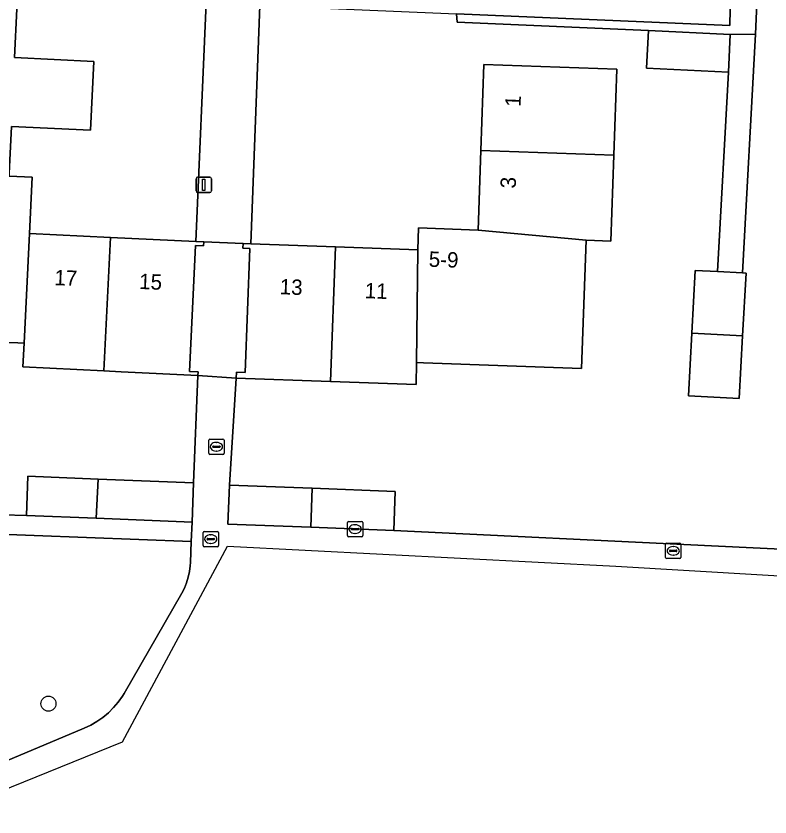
# Model space of a CAD drawing. Extents: x 158472 to 159562, y 388525 to 389606.
# Drawn here: x 159024.3 to 159073.4, y 388530.2 to 388582.4 of the extents above; entities that cross this region are included whole.
import ezdxf

# ---------------------------------------------------------------- set-up
doc = ezdxf.new("R2010")
doc.units = 0
for name, color, linetype in [('IMGEO_Boom', 7, 'Continuous'), ('IMGEO_Erf', 7, 'Continuous'), ('IMGEO_Fietspad_open', 7, 'Continuous'), ('IMGEO_Groenvoorziening', 7, 'Continuous'), ('IMGEO_Kolk', 7, 'Continuous'), ('IMGEO_Lichtmast', 7, 'Continuous'), ('IMGEO_Muur', 7, 'Continuous'), ('IMGEO_Pand', 7, 'Continuous'), ('IMGEO_Pand_nummerreeks', 7, 'Continuous'), ('IMGEO_Rijbaan_lokaal_open', 7, 'Continuous'), ('IMGEO_Rioolput', 7, 'Continuous'), ('IMGEO_Voetpad_open', 7, 'Continuous')]:
    doc.layers.add(name, color=color, linetype=linetype)

msp = doc.modelspace()

# ---------------------------------------------------------------- linework, layer by layer
at = {"layer": 'IMGEO_Boom'}
msp.add_circle((159026.448, 388537.59), 0.489, dxfattribs=at)
at = {"layer": 'IMGEO_Erf'}
for points in [[(159030.147, 388590.079), (159030.021, 388590.479), (159027.022, 388590.623), (159026.791, 388585.828), (159024.536, 388585.936), (159024.386, 388582.821), (159024.233, 388579.656), (159029.39, 388579.407), (159029.173, 388574.92), (159024.038, 388575.168), (159023.89, 388572.105), (159023.882, 388571.935), (159025.383, 388571.86), (159025.206, 388568.195), (159030.493, 388567.94), (159036.047, 388567.672), (159036.701, 388583.22), (159035.299, 388583.862)], [(159040.21, 388583.043), (159039.615, 388567.522), (159045.116, 388567.328), (159050.485, 388567.139), (159050.535, 388568.562), (159054.4, 388568.426), (159054.583, 388573.603), (159054.78, 388579.197), (159063.431, 388578.892), (159063.234, 388573.298), (159063.037, 388567.705), (159061.426, 388567.761), (159061.132, 388559.413), (159050.854, 388559.775), (159050.389, 388559.791), (159050.37, 388558.377), (159044.806, 388558.573), (159038.66, 388558.789), (159038.221, 388551.82), (159043.615, 388551.61), (159049.01, 388551.4), (159048.912, 388548.861), (159069.588, 388547.872), (159089.474, 388546.92)], [(159072.545, 388583.165), (159072.454, 388581.166), (159071.607, 388565.63), (159071.838, 388565.617), (159071.615, 388561.534), (159071.393, 388557.456), (159068.092, 388557.636), (159068.314, 388561.715), (159068.537, 388565.797), (159069.983, 388565.718), (159070.69, 388578.692), (159065.359, 388578.962), (159065.483, 388581.425), (159053.038, 388581.96), (159053.006, 388582.499)], [(159023.481, 388549.894), (159025.01, 388549.835), (159025.109, 388552.391), (159029.682, 388552.214), (159035.887, 388551.973), (159036.168, 388558.949), (159031.175, 388559.195), (159030.045, 388559.251), (159024.787, 388559.51), (159024.862, 388561.065), (159024.462, 388561.08), (159016.089, 388561.387)]]:
    msp.add_lwpolyline(points, dxfattribs=at)
at = {"layer": 'IMGEO_Fietspad_open'}
for points in [[(159089.474, 388546.92), (159069.588, 388547.872), (159048.912, 388548.861), (159043.515, 388549.071), (159038.123, 388549.281), (159038.221, 388551.82), (159038.66, 388558.789), (159036.168, 388558.949), (159035.887, 388551.973), (159035.788, 388549.417), (159035.735, 388548.148), (159035.679, 388546.783), (159035.668, 388546.57), (159035.623, 388546.194), (159035.545, 388545.823), (159035.433, 388545.461), (159035.29, 388545.111), (159035.116, 388544.774), (159031.363, 388538.256), (159031.259, 388538.083), (159030.99, 388537.694), (159030.688, 388537.331), (159030.355, 388536.997), (159029.992, 388536.693), (159029.605, 388536.424), (159029.195, 388536.19), (159028.765, 388535.993), (159020.362, 388532.463)], [(159019.207, 388530.214), (159031.272, 388535.104), (159038.098, 388547.837), (159063.371, 388546.546), (159087.583, 388545.104)]]:
    msp.add_lwpolyline(points, dxfattribs=at)
at = {"layer": 'IMGEO_Groenvoorziening'}
msp.add_lwpolyline([(159035.623, 388546.194), (159035.668, 388546.57), (159035.679, 388546.783), (159035.735, 388548.148), (159022.089, 388548.677), (159022.138, 388549.946), (159018.895, 388550.072), (159013.79, 388548.723), (159020.362, 388532.463), (159028.765, 388535.993), (159029.195, 388536.19), (159029.605, 388536.424), (159029.992, 388536.693), (159030.355, 388536.997), (159030.688, 388537.331), (159030.99, 388537.694), (159031.259, 388538.083), (159031.363, 388538.256), (159035.116, 388544.774), (159035.29, 388545.111), (159035.433, 388545.461), (159035.545, 388545.823)], close=True, dxfattribs=at)
at = {"layer": 'IMGEO_Kolk'}
for p, q in [((159036.949, 388554.819), (159037.801, 388554.819)), ((159036.874, 388553.893), (159036.874, 388554.745)), ((159037.133, 388554.313), (159037.133, 388554.325)), ((159037.571, 388554.276), (159037.173, 388554.276)), ((159037.176, 388554.362), (159037.574, 388554.362)), ((159037.362, 388554.599), (159037.387, 388554.599)), ((159037.617, 388554.325), (159037.617, 388554.313)), ((159037.875, 388554.745), (159037.875, 388553.893)), ((159037.801, 388553.819), (159036.949, 388553.819)), ((159037.385, 388554.039), (159037.36, 388554.039)), ((159045.899, 388548.532), (159045.899, 388549.384)), ((159045.974, 388549.458), (159046.826, 388549.458)), ((159046.387, 388549.238), (159046.412, 388549.238)), ((159046.9, 388549.384), (159046.9, 388548.532)), ((159046.158, 388548.952), (159046.158, 388548.964)), ((159046.596, 388548.915), (159046.198, 388548.915)), ((159046.201, 388549.001), (159046.599, 388549.001)), ((159046.41, 388548.678), (159046.385, 388548.678)), ((159046.642, 388548.964), (159046.642, 388548.952)), ((159046.826, 388548.458), (159045.974, 388548.458)), ((159066.676, 388548.04), (159067.528, 388548.04)), ((159066.601, 388547.114), (159066.601, 388547.966)), ((159066.86, 388547.534), (159066.86, 388547.546)), ((159067.298, 388547.497), (159066.9, 388547.497)), ((159066.903, 388547.583), (159067.301, 388547.583)), ((159067.089, 388547.82), (159067.114, 388547.82)), ((159067.344, 388547.546), (159067.344, 388547.534)), ((159067.602, 388547.966), (159067.602, 388547.114)), ((159067.528, 388547.04), (159066.676, 388547.04)), ((159067.112, 388547.26), (159067.087, 388547.26))]:
    msp.add_line(p, q, dxfattribs=at)
for points in [[(159036.949, 388554.819), (159037.801, 388554.819)], [(159036.874, 388553.893), (159036.874, 388554.745)], [(159037.875, 388554.745), (159037.875, 388553.893)], [(159037.801, 388553.819), (159036.949, 388553.819)], [(159045.899, 388548.532), (159045.899, 388549.384)], [(159045.974, 388549.458), (159046.826, 388549.458)], [(159046.9, 388549.384), (159046.9, 388548.532)], [(159046.826, 388548.458), (159045.974, 388548.458)], [(159066.676, 388548.04), (159067.528, 388548.04)], [(159066.601, 388547.114), (159066.601, 388547.966)], [(159067.602, 388547.966), (159067.602, 388547.114)], [(159067.528, 388547.04), (159066.676, 388547.04)]]:
    msp.add_lwpolyline(points, dxfattribs=at)
for centre, radius, start, end in [((159036.951, 388554.743), 0.0765, 91.552, 178.448), ((159036.951, 388554.743), 0.0765, 91.552, 178.448), ((159037.799, 388554.743), 0.0765, 1.552, 88.448), ((159037.799, 388554.743), 0.0765, 1.552, 88.448), ((159037.173, 388554.322), 0.0403, 85.8775, 175.7526), ((159037.17, 388554.312), 0.0366, 178.938, 274.7102), ((159037.574, 388554.319), 0.043, 264.8664, 352.4533), ((159037.578, 388554.324), 0.0386, 1.7309, 96.639), ((159036.951, 388553.895), 0.0765, 181.552, 268.448), ((159036.951, 388553.895), 0.0765, 181.552, 268.448), ((159037.799, 388553.895), 0.0765, 271.552, 358.448), ((159037.799, 388553.895), 0.0765, 271.552, 358.448), ((159045.976, 388549.382), 0.0765, 91.552, 178.448), ((159045.976, 388549.382), 0.0765, 91.552, 178.448), ((159046.824, 388549.382), 0.0765, 1.552, 88.448), ((159046.824, 388549.382), 0.0765, 1.552, 88.448), ((159045.976, 388548.534), 0.0765, 181.552, 268.448), ((159045.976, 388548.534), 0.0765, 181.552, 268.448), ((159046.198, 388548.961), 0.0403, 85.8775, 175.7526), ((159046.195, 388548.951), 0.0366, 178.938, 274.7102), ((159046.599, 388548.958), 0.043, 264.8664, 352.4533), ((159046.603, 388548.963), 0.0386, 1.7309, 96.639), ((159046.824, 388548.534), 0.0765, 271.552, 358.448), ((159046.824, 388548.534), 0.0765, 271.552, 358.448), ((159066.678, 388547.964), 0.0765, 91.552, 178.448), ((159066.678, 388547.964), 0.0765, 91.552, 178.448), ((159067.526, 388547.964), 0.0765, 1.552, 88.448), ((159067.526, 388547.964), 0.0765, 1.552, 88.448), ((159066.9, 388547.543), 0.0403, 85.8775, 175.7526), ((159066.897, 388547.533), 0.0366, 178.938, 274.7102), ((159067.301, 388547.54), 0.043, 264.8664, 352.4533), ((159067.305, 388547.545), 0.0386, 1.7309, 96.639), ((159066.678, 388547.116), 0.0765, 181.552, 268.448), ((159066.678, 388547.116), 0.0765, 181.552, 268.448), ((159067.526, 388547.116), 0.0765, 271.552, 358.448), ((159067.526, 388547.116), 0.0765, 271.552, 358.448)]:
    msp.add_arc(centre, radius, start, end, dxfattribs=at)
for centre, major_axis, ratio, start_param, end_param in [((159037.361, 388554.319), (-0.387, 0.002), 0.722429, 4.712389, 7.853982), ((159037.386, 388554.319), (-0.39, 0.002), 0.717154, 1.570796, 4.712389), ((159046.386, 388548.958), (-0.387, 0.002), 0.722429, 4.712389, 7.853982), ((159046.411, 388548.958), (-0.39, 0.002), 0.717154, 1.570796, 4.712389), ((159067.088, 388547.54), (-0.387, 0.002), 0.722429, 4.712389, 7.853982), ((159067.113, 388547.54), (-0.39, 0.002), 0.717154, 1.570796, 4.712389)]:
    msp.add_ellipse(centre, major_axis=major_axis, ratio=ratio, start_param=start_param, end_param=end_param, dxfattribs=at)
at = {"layer": 'IMGEO_Lichtmast'}
for p, q in [((159036.056, 388570.966), (159036.056, 388571.766)), ((159036.056, 388571.766), (159036.056, 388570.966)), ((159036.156, 388571.866), (159036.946, 388571.866)), ((159036.946, 388571.866), (159036.156, 388571.866)), ((159037.046, 388571.766), (159037.046, 388570.966)), ((159037.046, 388570.966), (159037.046, 388571.766)), ((159036.946, 388570.866), (159036.156, 388570.866)), ((159036.156, 388570.866), (159036.946, 388570.866))]:
    msp.add_line(p, q, dxfattribs=at)
msp.add_lwpolyline([(159036.476, 388571.741), (159036.626, 388571.741), (159036.626, 388570.991), (159036.476, 388570.991), (159036.476, 388571.741)], dxfattribs=at)
for centre, start, end in [((159036.156, 388571.766), 90, 180), ((159036.156, 388571.766), 90, 180), ((159036.946, 388571.766), 0, 90), ((159036.946, 388571.766), 360, 90), ((159036.156, 388570.966), 180, 270), ((159036.156, 388570.966), 180, 270), ((159036.946, 388570.966), 270, 0), ((159036.946, 388570.966), 270, 0)]:
    msp.add_arc(centre, 0.1, start, end, dxfattribs=at)
at = {"layer": 'IMGEO_Muur'}
msp.add_lwpolyline([(159048.912, 388548.861), (159069.588, 388547.872)], dxfattribs=at)
at = {"layer": 'IMGEO_Pand'}
for points in [[(159024.386, 388582.821), (159015.65, 388583.238), (159015.494, 388580.014), (159010.941, 388580.234), (159010.723, 388575.711), (159010.479, 388570.654), (159012.383, 388570.509), (159015.145, 388572.37), (159016.616, 388572.297), (159023.882, 388571.935), (159023.89, 388572.105), (159024.038, 388575.168), (159029.173, 388574.92), (159029.39, 388579.407), (159024.233, 388579.656)], [(159070.815, 388581.156), (159065.483, 388581.425), (159065.359, 388578.962), (159070.69, 388578.692)], [(159063.234, 388573.298), (159063.431, 388578.892), (159054.78, 388579.197), (159054.583, 388573.603)], [(159063.234, 388573.298), (159054.583, 388573.603), (159054.4, 388568.426), (159061.426, 388567.761), (159063.037, 388567.705)], [(159025.206, 388568.195), (159025.383, 388571.86), (159023.882, 388571.935), (159016.616, 388572.297), (159016.608, 388572.139), (159016.597, 388571.909), (159016.089, 388561.387), (159024.462, 388561.08), (159024.862, 388561.065)], [(159061.426, 388567.761), (159054.4, 388568.426), (159050.535, 388568.562), (159050.485, 388567.139), (159050.389, 388559.791), (159050.854, 388559.775), (159061.132, 388559.413)], [(159030.493, 388567.94), (159025.206, 388568.195), (159024.862, 388561.065), (159024.787, 388559.51), (159030.045, 388559.251)], [(159030.493, 388567.94), (159030.045, 388559.251), (159031.175, 388559.195), (159036.168, 388558.949), (159036.18, 388559.192), (159035.621, 388559.219), (159036.016, 388567.42), (159036.534, 388567.395), (159036.547, 388567.648), (159036.047, 388567.672)], [(159045.116, 388567.328), (159039.615, 388567.522), (159039.107, 388567.54), (159039.096, 388567.24), (159039.54, 388567.224), (159039.256, 388559.153), (159038.673, 388559.173), (159038.66, 388558.789), (159044.806, 388558.573)], [(159050.485, 388567.139), (159045.116, 388567.328), (159044.806, 388558.573), (159050.37, 388558.377), (159050.389, 388559.791)], [(159071.838, 388565.617), (159071.607, 388565.63), (159069.983, 388565.718), (159068.537, 388565.797), (159068.314, 388561.715), (159071.615, 388561.534)], [(159068.314, 388561.715), (159068.092, 388557.636), (159071.393, 388557.456), (159071.615, 388561.534)], [(159029.55, 388549.659), (159029.682, 388552.214), (159025.109, 388552.391), (159025.01, 388549.835)], [(159029.55, 388549.659), (159035.788, 388549.417), (159035.887, 388551.973), (159029.682, 388552.214)], [(159043.615, 388551.61), (159038.221, 388551.82), (159038.123, 388549.281), (159043.515, 388549.071)], [(159043.615, 388551.61), (159043.515, 388549.071), (159048.912, 388548.861), (159049.01, 388551.4)]]:
    msp.add_lwpolyline(points, close=True, dxfattribs=at)
at = {"layer": 'IMGEO_Rijbaan_lokaal_open'}
msp.add_lwpolyline([(159035.299, 388583.862), (159036.701, 388583.22), (159040.21, 388583.043), (159053.006, 388582.499), (159070.792, 388581.748), (159070.857, 388584.967)], dxfattribs=at)
at = {"layer": 'IMGEO_Rioolput'}
for p, q in [((159036.51, 388547.88), (159036.51, 388548.732)), ((159036.585, 388548.806), (159037.437, 388548.806)), ((159036.998, 388548.586), (159037.023, 388548.586)), ((159037.511, 388548.732), (159037.511, 388547.88)), ((159036.769, 388548.3), (159036.769, 388548.312)), ((159037.207, 388548.263), (159036.809, 388548.263)), ((159036.812, 388548.349), (159037.21, 388548.349)), ((159037.021, 388548.026), (159036.996, 388548.026)), ((159037.253, 388548.312), (159037.253, 388548.3)), ((159037.437, 388547.806), (159036.585, 388547.806))]:
    msp.add_line(p, q, dxfattribs=at)
for points in [[(159036.51, 388547.88), (159036.51, 388548.732)], [(159036.585, 388548.806), (159037.437, 388548.806)], [(159037.511, 388548.732), (159037.511, 388547.88)], [(159037.437, 388547.806), (159036.585, 388547.806)]]:
    msp.add_lwpolyline(points, dxfattribs=at)
for centre, radius, start, end in [((159036.587, 388548.73), 0.0765, 91.552, 178.448), ((159036.587, 388548.73), 0.0765, 91.552, 178.448), ((159037.435, 388548.73), 0.0765, 1.552, 88.448), ((159037.435, 388548.73), 0.0765, 1.552, 88.448), ((159036.809, 388548.309), 0.0403, 85.8775, 175.7526), ((159036.806, 388548.299), 0.0366, 178.938, 274.7102), ((159037.21, 388548.306), 0.043, 264.8664, 352.4533), ((159037.214, 388548.311), 0.0386, 1.7309, 96.639), ((159036.587, 388547.882), 0.0765, 181.552, 268.448), ((159036.587, 388547.882), 0.0765, 181.552, 268.448), ((159037.435, 388547.882), 0.0765, 271.552, 358.448), ((159037.435, 388547.882), 0.0765, 271.552, 358.448)]:
    msp.add_arc(centre, radius, start, end, dxfattribs=at)
for centre, major_axis, ratio, start_param, end_param in [((159036.997, 388548.306), (-0.387, 0.002), 0.722429, 4.712389, 7.853982), ((159037.022, 388548.306), (-0.39, 0.002), 0.717154, 1.570796, 4.712389)]:
    msp.add_ellipse(centre, major_axis=major_axis, ratio=ratio, start_param=start_param, end_param=end_param, dxfattribs=at)
at = {"layer": 'IMGEO_Voetpad_open'}
for points in [[(159098.908, 388585.279), (159100.763, 388584.018), (159099.598, 388587.182), (159087.035, 388584.258), (159073.615, 388584.846), (159070.857, 388584.967), (159070.792, 388581.748), (159053.006, 388582.499), (159053.038, 388581.96), (159065.483, 388581.425), (159070.815, 388581.156), (159072.454, 388581.166), (159072.545, 388583.165), (159087.353, 388582.51)], [(159039.615, 388567.522), (159040.21, 388583.043), (159036.701, 388583.22), (159036.047, 388567.672), (159036.547, 388567.648), (159039.107, 388567.54)], [(159072.454, 388581.166), (159070.815, 388581.156), (159070.69, 388578.692), (159069.983, 388565.718), (159071.607, 388565.63)], [(159038.673, 388559.173), (159039.256, 388559.153), (159039.54, 388567.224), (159039.096, 388567.24), (159039.107, 388567.54), (159036.547, 388567.648), (159036.534, 388567.395), (159036.016, 388567.42), (159035.621, 388559.219), (159036.18, 388559.192), (159036.168, 388558.949), (159038.66, 388558.789)], [(159035.788, 388549.417), (159029.55, 388549.659), (159025.01, 388549.835), (159023.481, 388549.894), (159022.138, 388549.946), (159022.089, 388548.677), (159035.735, 388548.148)]]:
    msp.add_lwpolyline(points, close=True, dxfattribs=at)

# ---------------------------------------------------------------- texts
at = {"layer": 'IMGEO_Pand_nummerreeks'}
for s, rotation, p in [('1', 87.7676, (159057.164, 388576.434)), ('3', 87.7676, (159056.851, 388571.119)), ('5-9', 357.9832, (159051.179, 388566.038)), ('17', 357.6108, (159026.814, 388564.84)), ('15', 357.6079, (159032.333, 388564.591)), ('13', 357.6079, (159041.478, 388564.25)), ('11', 357.6108, (159047.012, 388563.993))]:
    msp.add_text(s, height=1, rotation=rotation, dxfattribs=at).set_placement(p)

doc.saveas('drawing.dxf')
